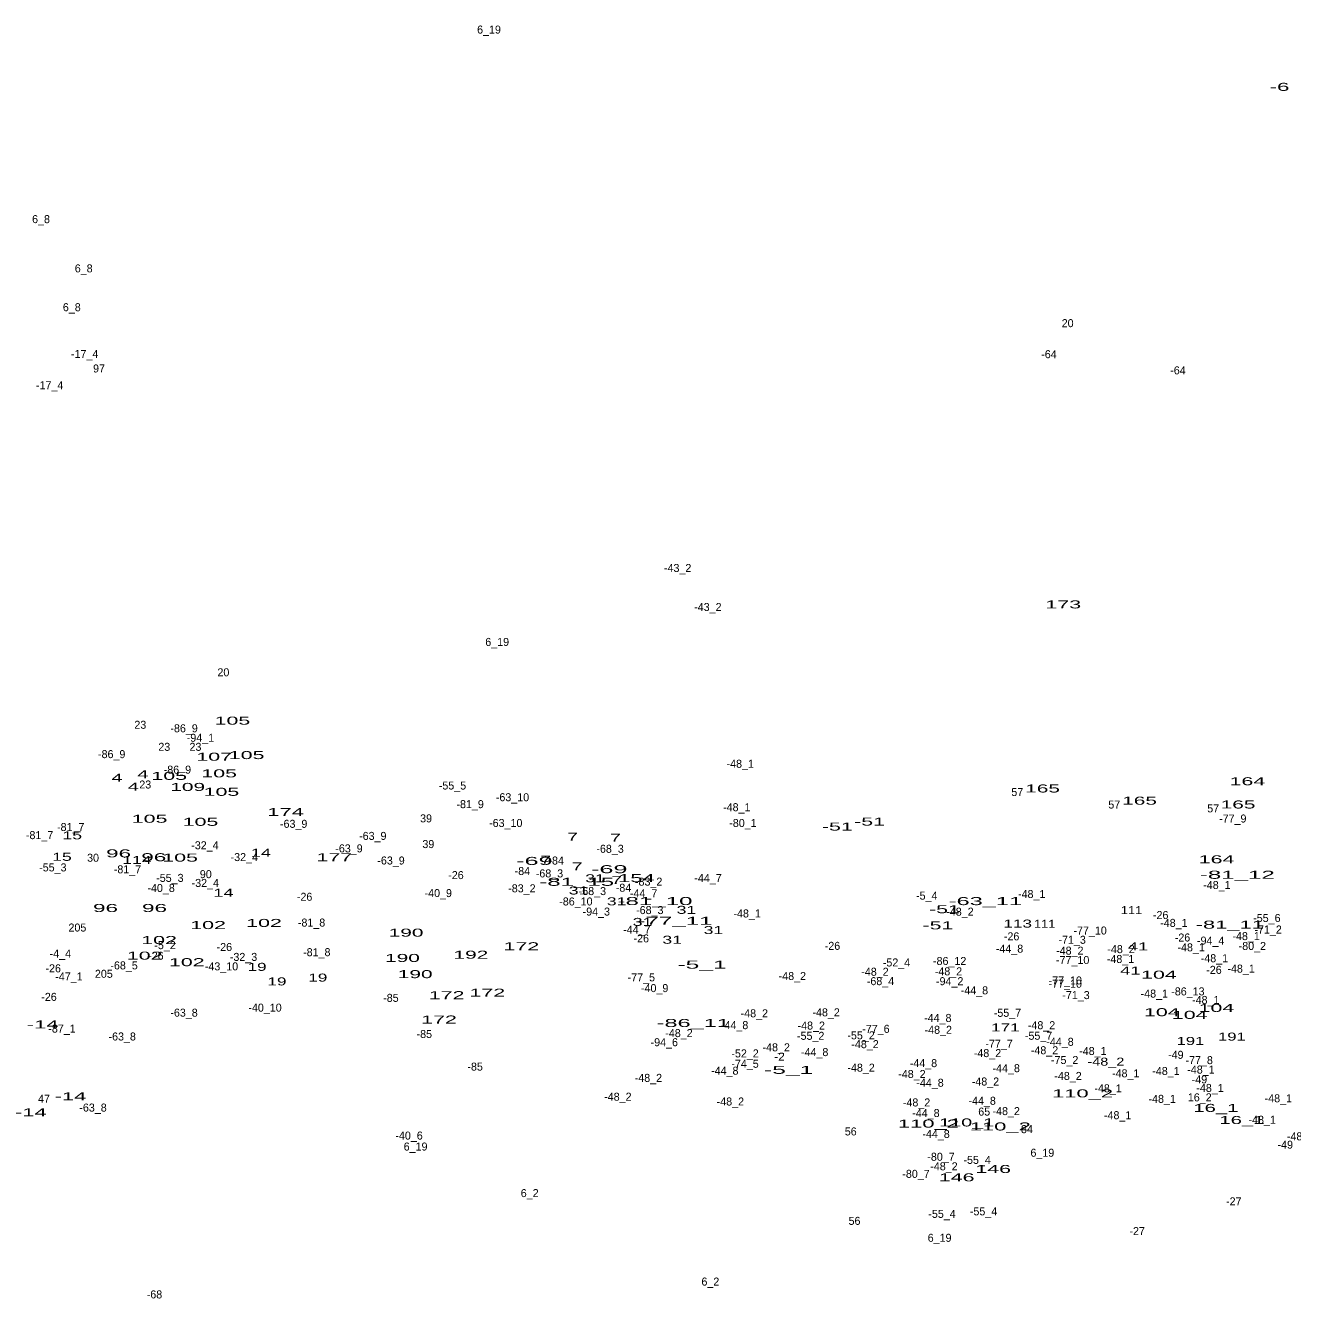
# Model space of a CAD drawing. Extents: x -659624 to -656248, y -1006345 to -1003555.
# Drawn here: x -657721 to -657087, y -1004867 to -1004230 of the extents above; entities that cross this region are included whole.
import ezdxf
from ezdxf.enums import TextEntityAlignment as Align

# ---------------------------------------------------------------- set-up
doc = ezdxf.new("R2010")
doc.units = 0
doc.header["$LTSCALE"] = 1.6
doc.layers.add('24', color=7, linetype='Continuous')

msp = doc.modelspace()

# ---------------------------------------------------------------- texts
at = {"layer": '24'}
for s, p in [('6_19', (-657489.02, -1004234.26)), ('6_8', (-657713.031, -1004329.01)), ('6_8', (-657691.691, -1004353.62)), ('6_8', (-657697.651, -1004373.04)), ('20', (-657199.671, -1004381.01)), ('-17_4', (-657691.216, -1004396.41)), ('-64', (-657209.015, -1004396.53)), ('97', (-657684.028, -1004403.65)), ('-64', (-657144.505, -1004404.59)), ('-17_4', (-657708.716, -1004412.01)), ('-43_2', (-657394.687, -1004503.37)), ('-43_2', (-657379.587, -1004522.88)), ('6_19', (-657484.93, -1004540.35)), ('20', (-657621.841, -1004555.53)), ('23', (-657663.387, -1004581.75)), ('-86_9', (-657641.493, -1004583.51)), ('23', (-657651.397, -1004592.78)), ('-94_1', (-657633.326, -1004588.26)), ('23', (-657635.807, -1004592.78)), ('-86_9', (-657677.693, -1004596.43)), ('-86_9', (-657644.843, -1004604.19)), ('-48_1', (-657363.39, -1004601.25)), ('23', (-657660.907, -1004611.61)), ('-55_5', (-657507.282, -1004612.12)), ('-63_10', (-657477.276, -1004617.97)), ('57', (-657224.853, -1004615.37)), ('-81_9', (-657498.462, -1004621.44)), ('-48_1', (-657365.12, -1004622.96)), ('57', (-657176.353, -1004621.64)), ('57', (-657126.903, -1004623.55)), ('-63_9', (-657586.693, -1004631.26)), ('39', (-657520.503, -1004628.55)), ('-63_10', (-657480.646, -1004630.84)), ('-80_1', (-657362.04, -1004630.84)), ('-77_9', (-657117.098, -1004628.62)), ('-81_7', (-657713.762, -1004636.91)), ('-81_7', (-657698.192, -1004632.88)), ('-63_9', (-657547.133, -1004637.31)), ('-32_4', (-657631.077, -1004641.98)), ('-63_9', (-657559.043, -1004643.55)), ('39', (-657519.363, -1004641.39)), ('-68_3', (-657428.488, -1004643.75)), ('30', (-657687.021, -1004648.22)), ('-32_4', (-657611.397, -1004647.88)), ('-63_9', (-657538.013, -1004649.59)), ('-84', (-657455.439, -1004649.62)), ('-55_3', (-657707.122, -1004653.05)), ('-81_7', (-657669.802, -1004654)), ('90', (-657630.647, -1004656.44)), ('-26', (-657505.54, -1004656.89)), ('-84', (-657472.329, -1004654.86)), ('-68_3', (-657458.788, -1004656.05)), ('-40_8', (-657652.981, -1004663.34)), ('-55_3', (-657648.602, -1004658.29)), ('-32_4', (-657630.887, -1004660.81)), ('-83_2', (-657472.582, -1004663.5)), ('-84', (-657421.759, -1004663.21)), ('-83_2', (-657409.192, -1004660.16)), ('-44_7', (-657379.496, -1004658.36)), ('-48_1', (-657125.04, -1004661.86)), ('-26', (-657581.23, -1004667.73)), ('-40_9', (-657514.396, -1004665.88)), ('-86_10', (-657445.566, -1004670.07)), ('-68_3', (-657437.338, -1004664.88)), ('-44_7', (-657411.696, -1004665.95)), ('-5_4', (-657270.128, -1004667.16)), ('-48_1', (-657217.64, -1004666.36)), ('-94_3', (-657435.362, -1004675.12)), ('-68_3', (-657408.618, -1004674.38)), ('-48_1', (-657359.94, -1004676.07)), ('-48_2', (-657253.527, -1004675.18)), ('-26', (-657153.14, -1004676.86)), ('205', (-657694.841, -1004683.11)), ('-81_8', (-657577.756, -1004680.62)), ('-48_1', (-657146.54, -1004680.78)), ('-55_6', (-657100.048, -1004678.34)), ('-44_7', (-657415.086, -1004684.15)), ('-26', (-657412.89, -1004688.52)), ('-26', (-657227.69, -1004687.52)), ('-71_3', (-657197.412, -1004689.23)), ('-77_10', (-657188.431, -1004684.6)), ('-26', (-657142.24, -1004688.09)), ('-94_4', (-657128.146, -1004689.62)), ('-48_1', (-657110.43, -1004687.39)), ('-71_2', (-657099.422, -1004684.09)), ('-4_4', (-657703.352, -1004696.11)), ('-5_2', (-657651.013, -1004691.92)), ('-26', (-657621.36, -1004692.84)), ('-81_8', (-657575.136, -1004695.43)), ('-26', (-657317.27, -1004692.27)), ('-44_8', (-657228.741, -1004693.66)), ('-48_2', (-657198.587, -1004694.66)), ('-48_2', (-657172.977, -1004693.9)), ('-48_1', (-657137.91, -1004693.02)), ('-80_2', (-657107.316, -1004692.32)), ('-68_5', (-657671.508, -1004702.04)), ('-26', (-657655.6, -1004697.22)), ('-43_10', (-657622.794, -1004702.52)), ('-32_3', (-657611.772, -1004697.79)), ('-52_4', (-657285.257, -1004700.57)), ('-86_12', (-657258.672, -1004699.82)), ('-77_10', (-657197.161, -1004699.35)), ('-48_1', (-657173.23, -1004698.83)), ('-48_1', (-657126.28, -1004698.45)), ('-26', (-657706.95, -1004703.5)), ('-47_1', (-657699.066, -1004707.58)), ('205', (-657681.621, -1004706.23)), ('-77_5', (-657412.854, -1004708.01)), ('-48_2', (-657337.337, -1004707.34)), ('-48_2', (-657296.017, -1004705.2)), ('-48_2', (-657259.277, -1004705.03)), ('-26', (-657126.51, -1004704.26)), ('-48_1', (-657112.94, -1004703.64)), ('-40_9', (-657406.186, -1004713.38)), ('-68_4', (-657293.252, -1004709.9)), ('-94_2', (-657258.652, -1004709.93)), ('-44_8', (-657246.291, -1004714.51)), ('-77_10', (-657200.851, -1004709.55)), ('-77_10', (-657200.851, -1004709.55)), ('-77_10', (-657200.851, -1004711.2)), ('-86_13', (-657139.542, -1004715.03)), ('-26', (-657709.04, -1004717.77)), ('-85', (-657538.075, -1004718.26)), ('-71_3', (-657195.502, -1004716.89)), ('-48_1', (-657156.33, -1004716.12)), ('-48_1', (-657130.61, -1004719.3)), ('-63_8', (-657641.518, -1004725.66)), ('-40_10', (-657601.018, -1004723.15)), ('-48_2', (-657356.347, -1004725.97)), ('-48_2', (-657320.447, -1004725.49)), ('-55_7', (-657229.758, -1004725.74)), ('-87_1', (-657702.552, -1004733.61)), ('-44_8', (-657366.201, -1004731.89)), ('-48_2', (-657327.877, -1004732.1)), ('-77_6', (-657295.538, -1004733.75)), ('-44_8', (-657264.611, -1004728.3)), ('-48_2', (-657264.377, -1004734.23)), ('-48_2', (-657212.727, -1004731.93)), ('-63_8', (-657672.438, -1004737.57)), ('-85', (-657521.375, -1004736.32)), ('-94_6', (-657401.368, -1004740.43)), ('-48_2', (-657394.037, -1004735.88)), ('-55_2', (-657328.162, -1004737.24)), ('-55_2', (-657302.972, -1004737)), ('-55_7', (-657214.218, -1004737.2)), ('-44_8', (-657203.501, -1004740.22)), ('-52_2', (-657360.972, -1004746.02)), ('-48_2', (-657345.407, -1004742.97)), ('-44_8', (-657326.171, -1004745.37)), ('-48_2', (-657300.997, -1004741.4)), ('-48_2', (-657239.757, -1004745.87)), ('-77_7', (-657233.979, -1004741.21)), ('-48_2', (-657211.237, -1004744.45)), ('-48_1', (-657187.06, -1004744.82)), ('-49', (-657145.575, -1004746.72)), ('-85', (-657495.955, -1004752.63)), ('-74_5', (-657360.992, -1004751.2)), ('-48_2', (-657302.967, -1004753.15)), ('-44_8', (-657271.781, -1004750.89)), ('-44_8', (-657230.391, -1004753.41)), ('-75_2', (-657201.168, -1004749.33)), ('-77_8', (-657133.894, -1004749.39)), ('-48_2', (-657409.327, -1004758.26)), ('-44_8', (-657371.121, -1004754.67)), ('-48_2', (-657277.537, -1004756.32)), ('-48_2', (-657199.477, -1004757.29)), ('-48_1', (-657170.64, -1004755.97)), ('-48_1', (-657150.5, -1004754.82)), ('-48_1', (-657133.01, -1004754.1)), ('-49', (-657133.785, -1004759.02)), ('-44_8', (-657268.491, -1004760.69)), ('-48_2', (-657240.767, -1004760.07)), ('-48_1', (-657179.47, -1004763.47)), ('-48_1', (-657128.47, -1004763.29)), ('47', (-657711.527, -1004768.65)), ('-48_2', (-657424.587, -1004767.67)), ('-48_2', (-657368.337, -1004770.06)), ('-48_2', (-657275.227, -1004770.54)), ('-44_8', (-657242.411, -1004769.7)), ('-48_1', (-657152.4, -1004768.74)), ('16_2', (-657133.614, -1004767.98)), ('-48_1', (-657094.32, -1004768.46)), ('-63_8', (-657687.028, -1004773.1)), ('-44_8', (-657270.531, -1004775.82)), ('65', (-657241.393, -1004775.12)), ('-48_2', (-657230.397, -1004774.86)), ('-48_1', (-657174.67, -1004776.91)), ('56', (-657308.143, -1004785.03)), ('84', (-657220.031, -1004783.88)), ('-48_1', (-657102.38, -1004779.21)), ('-40_6', (-657528.996, -1004787.1)), ('-44_8', (-657265.481, -1004786.29)), ('-49', (-657090.855, -1004791.66)), ('-48_1', (-657083.18, -1004787.47)), ('6_19', (-657525.73, -1004792.59)), ('-80_7', (-657262.992, -1004797.69)), ('6_19', (-657212.32, -1004795.68)), ('-48_2', (-657261.527, -1004802.46)), ('-55_4', (-657244.927, -1004799.25)), ('-80_7', (-657275.502, -1004806.23)), ('6_2', (-657468.681, -1004815.85)), ('-27', (-657116.601, -1004819.98)), ('56', (-657306.243, -1004829.73)), ('-55_4', (-657262.497, -1004826.23)), ('-55_4', (-657241.727, -1004824.97)), ('-27', (-657164.911, -1004834.82)), ('6_19', (-657263.7, -1004838.19)), ('6_2', (-657378.331, -1004860.08)), ('-68', (-657656.3, -1004866.5))]:
    msp.add_text(s, height=4, dxfattribs=at).set_placement(p, align=Align.CENTER)
for s, width, p in [('-6', 2.1, (-657093.739, -1004262.89)), ('173', 2, (-657201.853, -1004521.59)), ('105', 2, (-657617.334, -1004579.69)), ('107', 2, (-657626.449, -1004597.72)), ('105', 2, (-657610.224, -1004596.9)), ('4', 1.9, (-657662.127, -1004606.5)), ('105', 2, (-657623.964, -1004606.04)), ('4', 1.9, (-657675.007, -1004608.23)), ('4', 1.9, (-657666.837, -1004612.65)), ('105', 2, (-657648.924, -1004607.28)), ('109', 1.95, (-657639.699, -1004612.83)), ('164', 2, (-657109.788, -1004609.99)), ('105', 2, (-657622.814, -1004615.27)), ('165', 1.95, (-657212.203, -1004613.6)), ('165', 1.95, (-657163.703, -1004619.69)), ('174', 2.05, (-657590.728, -1004625.37)), ('165', 1.95, (-657114.453, -1004621.59)), ('105', 2, (-657658.754, -1004628.72)), ('105', 2, (-657633.284, -1004630.26)), ('-51', 2, (-657298.711, -1004630.16)), ('15', 1.65, (-657697.417, -1004637.01)), ('7', 1.8, (-657447.186, -1004637.67)), ('7', 1.8, (-657425.786, -1004638.24)), ('-51', 2, (-657314.831, -1004632.65)), ('15', 1.65, (-657702.557, -1004647.76)), ('96', 2.1, (-657674.251, -1004646.04)), ('114', 1.65, (-657665.089, -1004649.33)), ('96', 2.1, (-657656.661, -1004647.96)), ('105', 2, (-657643.474, -1004648.15)), ('14', 1.7, (-657603.093, -1004645.74)), ('177', 2, (-657566.347, -1004647.94)), ('-69', 2.35, (-657466.333, -1004649.81)), ('7', 1.8, (-657460.666, -1004649.23)), ('164', 2, (-657125.198, -1004648.99)), ('7', 1.8, (-657444.926, -1004652.53)), ('-69', 2.35, (-657428.893, -1004653.94)), ('-81_12', 2.25, (-657114.837, -1004656.73)), ('-81_15', 2.25, (-657445.167, -1004660.25)), ('31', 1.65, (-657435.997, -1004658.48)), ('7', 1.8, (-657425.176, -1004659.28)), ('154', 2.05, (-657415.303, -1004658.42)), ('14', 1.7, (-657621.823, -1004665.72)), ('31', 1.65, (-657444.217, -1004664.59)), ('31', 1.65, (-657425.197, -1004670.01)), ('-81_10', 2.25, (-657406.014, -1004669.87)), ('-63_11', 2.2, (-657240.793, -1004669.89)), ('96', 2.1, (-657680.791, -1004673.35)), ('96', 2.1, (-657656.281, -1004673.35)), ('31', 1.65, (-657390.287, -1004674.27)), ('-51', 2, (-657261.261, -1004673.95)), ('111', 1.2, (-657167.72, -1004674.42)), ('102', 2, (-657629.494, -1004681.87)), ('102', 2, (-657601.514, -1004680.81)), ('31', 1.65, (-657412.267, -1004680.3)), ('-77_11', 2.25, (-657396.017, -1004679.75)), ('-51', 2, (-657264.531, -1004682.02)), ('113', 1.6, (-657224.644, -1004681.13)), ('111', 1.2, (-657211.16, -1004681.24)), ('-81_11', 2.05, (-657118.584, -1004681.66)), ('102', 2, (-657654.004, -1004689.36)), ('190', 1.95, (-657530.499, -1004685.66)), ('31', 1.65, (-657397.427, -1004689.21)), ('31', 1.65, (-657376.797, -1004684.36)), ('172', 2, (-657472.843, -1004692.47)), ('41', 1.7, (-657164.453, -1004692.57)), ('102', 2, (-657661.204, -1004697.15)), ('102', 2, (-657640.154, -1004700.42)), ('190', 1.95, (-657532.299, -1004698.31)), ('192', 1.95, (-657498.083, -1004696.69)), ('-5_1', 2.3, (-657382.491, -1004701.65)), ('19', 1.6, (-657605.003, -1004702.76)), ('19', 1.6, (-657574.613, -1004708.13)), ('190', 1.95, (-657525.929, -1004706.4)), ('41', 1.7, (-657168.323, -1004704.61)), ('104', 2, (-657154.029, -1004706.67)), ('19', 1.6, (-657595.053, -1004710.04)), ('172', 2, (-657510.203, -1004716.92)), ('172', 2, (-657489.863, -1004715.68)), ('104', 2, (-657152.589, -1004725.42)), ('104', 2, (-657138.649, -1004726.77)), ('104', 2, (-657125.289, -1004723.31)), ('-14', 2.05, (-657712.206, -1004731.54)), ('172', 2, (-657514.013, -1004729.1)), ('-86_11', 2.2, (-657386.873, -1004730.82)), ('171', 1.6, (-657230.799, -1004733.03)), ('191', 1.55, (-657138.279, -1004739.81)), ('191', 1.55, (-657117.549, -1004737.62)), ('-2', 1.1, (-657343.75, -1004747.64)), ('-48_2', 1.35, (-657180.55, -1004750.14)), ('-5_1', 2.3, (-657339.181, -1004754.24)), ('110_2', 2.05, (-657192.211, -1004766.01)), ('-14', 2.05, (-657698.326, -1004767.5)), ('-14', 2.05, (-657718.096, -1004775.49)), ('16_1', 1.9, (-657125.54, -1004773.27)), ('110_2', 2.05, (-657269.301, -1004781.1)), ('110_1', 1.85, (-657250.157, -1004780.53)), ('110_2', 2.05, (-657233.361, -1004782.54)), ('16_1', 1.9, (-657112.51, -1004779.33)), ('146', 2, (-657236.908, -1004803.79)), ('146', 2, (-657255.168, -1004807.97))]:
    msp.add_text(s, height=4, dxfattribs=dict(at, width=width)).set_placement(p, align=Align.CENTER)

doc.saveas('drawing.dxf')
